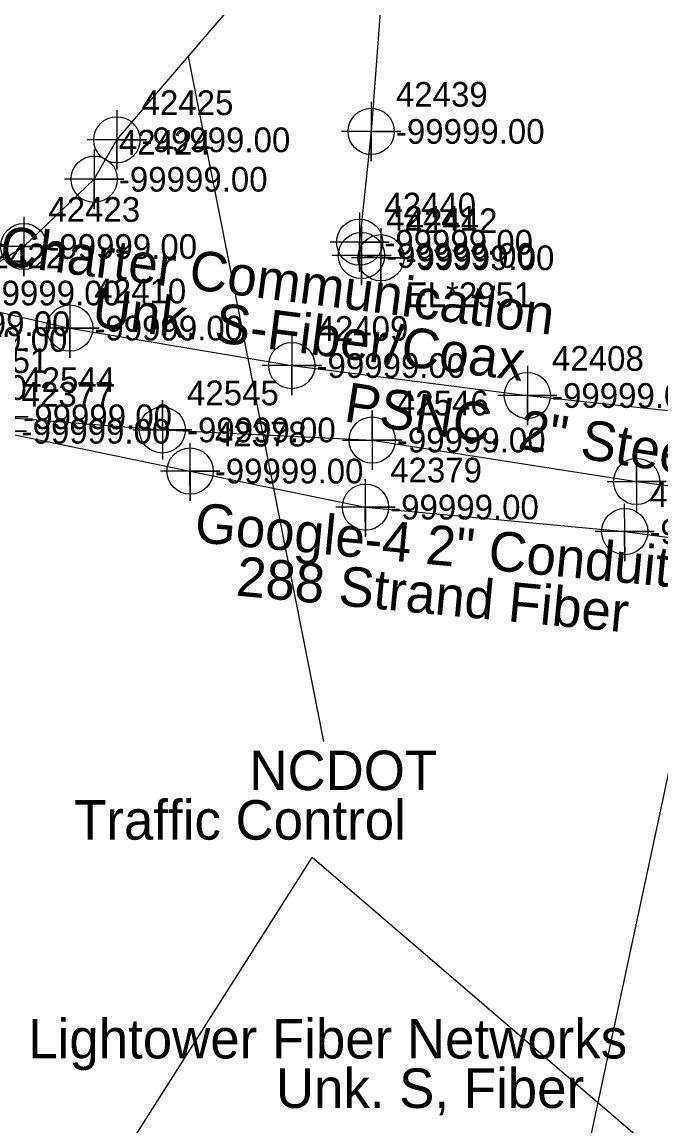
# Model space of a CAD drawing. Extents: x 2083698 to 2094313, y 743246 to 752873.
# Drawn here: x 2093709.1 to 2093773.8, y 746626.1 to 746737.9 of the extents above; entities that cross this region are included whole.
import ezdxf

# ---------------------------------------------------------------- set-up
doc = ezdxf.new("R2010")
doc.units = 0
for name, color, linetype in [('COGO Default Chain', 7, 'Continuous'), ('COGO Default Curve', 7, 'Continuous'), ('Default Symbol CELL', 7, 'Continuous'), ('Default Symbol Cogo Number', 7, 'Continuous'), ('Exist Property Iron Pin Leader', 7, 'Continuous'), ('Exist Property Iron Pin Text', 7, 'Continuous'), ('Exist Property Line Leader', 7, 'Continuous'), ('Exist Property Monument Leader', 7, 'Continuous'), ('Exist Property Monument Text', 7, 'Continuous'), ('Exist Right of Way Line Leader', 7, 'Continuous'), ('Exist Right of Way Line Text', 7, 'Continuous'), ('Exist Utilities Gas UG Line SUE LOS B', 7, 'Continuous'), ('Exist Utilities Gas UG Line SUE LOS B Text', 7, 'Continuous'), ('Exist Utilities Power Joint Use Telephone Cogo Elevation', 7, 'Continuous'), ('Exist Utilities Power UG Cable SUE LOS B', 7, 'Continuous'), ('Exist Utilities Power UG Cable SUE LOS B Leader', 7, 'Continuous'), ('Exist Utilities Power UG Cable SUE LOS B Text', 7, 'Continuous'), ('Exist Utilities Telephone UG Conduit SUE LOS B', 7, 'Continuous'), ('Exist Utilities Telephone UG Conduit SUE LOS B Text', 7, 'Continuous'), ('Exist Utilities TV UG Cable SUE LOS B', 7, 'Continuous'), ('Exist Utilities TV UG Cable SUE LOS B Text', 7, 'Continuous'), ('Exist Utilities Water UG Line SUE LOS B', 7, 'Continuous'), ('Old_Level_20', 7, 'Continuous'), ('Scratch_Level_2', 7, 'Continuous')]:
    doc.layers.add(name, color=color, linetype=linetype)

msp = doc.modelspace()

# ---------------------------------------------------------------- linework, layer by layer
at = {"layer": 'COGO Default Curve'}
for points in [[(2093703.71, 746697.9), (2093709.71, 746697.9), (2093706.71, 746697.9), (2093706.71, 746700.9), (2093706.71, 746694.9)], [(2093720.29, 746696.57), (2093726.29, 746696.57), (2093723.29, 746696.57), (2093723.29, 746699.57), (2093723.29, 746693.57)], [(2093741.54, 746695.55), (2093747.54, 746695.55), (2093744.54, 746695.55), (2093744.54, 746698.55), (2093744.54, 746692.55)], [(2093768.32, 746691.36), (2093774.32, 746691.36), (2093771.32, 746691.36), (2093771.32, 746694.36), (2093771.32, 746688.36)]]:
    msp.add_lwpolyline(points, dxfattribs=at)
for centre in [(2093723.29, 746696.57), (2093744.54, 746695.55), (2093771.32, 746691.36)]:
    msp.add_circle(centre, 2.34, dxfattribs=at)
at = {"layer": 'Exist Property Iron Pin Text'}
for points in [[(2093718.69, 746728.94), (2093718.69, 746722.94), (2093718.69, 746725.94), (2093721.69, 746725.94), (2093715.69, 746725.94)], [(2093744.44, 746729.79), (2093744.44, 746723.79), (2093744.44, 746726.79), (2093747.44, 746726.79), (2093741.44, 746726.79)], [(2093716.39, 746724.95), (2093716.39, 746718.95), (2093716.39, 746721.95), (2093719.39, 746721.95), (2093713.39, 746721.95)], [(2093709.25, 746718.14), (2093709.25, 746712.14), (2093709.25, 746715.14), (2093712.25, 746715.14), (2093706.25, 746715.14)], [(2093743.27, 746718.58), (2093743.27, 746712.58), (2093743.27, 746715.58), (2093746.27, 746715.58), (2093740.27, 746715.58)], [(2093743.45, 746717.23), (2093743.45, 746711.23), (2093743.45, 746714.23), (2093746.45, 746714.23), (2093740.45, 746714.23)], [(2093745.43, 746717), (2093745.43, 746711), (2093745.43, 746714), (2093748.43, 746714), (2093742.43, 746714)]]:
    msp.add_lwpolyline(points, dxfattribs=at)
for centre in [(2093744.44, 746726.79), (2093718.69, 746725.94), (2093716.39, 746721.95), (2093743.27, 746715.58), (2093709.25, 746715.14), (2093743.45, 746714.23), (2093745.43, 746714)]:
    msp.add_circle(centre, 2.34, dxfattribs=at)
at = {"layer": 'Exist Property Line Leader'}
for points in [[(2093713.91, 746709.88), (2093713.91, 746703.88), (2093713.91, 746706.88), (2093716.91, 746706.88), (2093710.91, 746706.88)], [(2093736.4, 746706.09), (2093736.4, 746700.09), (2093736.4, 746703.09), (2093739.4, 746703.09), (2093733.4, 746703.09)], [(2093760.25, 746703.06), (2093760.25, 746697.06), (2093760.25, 746700.06), (2093763.25, 746700.06), (2093757.25, 746700.06)]]:
    msp.add_lwpolyline(points, dxfattribs=at)
for centre in [(2093713.91, 746706.88), (2093736.4, 746703.09), (2093760.25, 746700.06)]:
    msp.add_circle(centre, 2.34, dxfattribs=at)
at = {"layer": 'Exist Right of Way Line Text'}
for points in [[(2093706.51, 746699.25), (2093706.54, 746693.44), (2093706.52, 746696.44), (2093709.54, 746696.44), (2093703.54, 746696.44)], [(2093726.07, 746695.23), (2093726.1, 746689.41), (2093726.09, 746692.41), (2093729.1, 746692.41), (2093723.1, 746692.41)], [(2093743.83, 746691.58), (2093743.86, 746685.76), (2093743.84, 746688.76), (2093746.86, 746688.76), (2093740.86, 746688.76)], [(2093770.07, 746689.09), (2093770.11, 746683.28), (2093770.09, 746686.28), (2093773.11, 746686.28), (2093767.11, 746686.28)]]:
    msp.add_lwpolyline(points, dxfattribs=at)
for centre in [(2093726.1, 746692.41), (2093743.86, 746688.76), (2093770.11, 746686.28)]:
    msp.add_circle(centre, 2.34, dxfattribs=at)
at = {"layer": 'Exist Utilities Gas UG Line SUE LOS B'}
msp.add_lwpolyline([(2093505.93, 746723.61), (2093532.22, 746720.11), (2093552.79, 746715.66), (2093607.51, 746708.06), (2093632.22, 746704.2), (2093661.04, 746701.95), (2093669.46, 746700.88), (2093683.89, 746699.44), (2093691.32, 746698.74), (2093706.71, 746697.9), (2093723.29, 746696.57), (2093744.54, 746695.55), (2093771.32, 746691.36), (2093802.14, 746687.34), (2093813.25, 746684.15), (2093821.63, 746681.65), (2093825.52, 746680.89), (2093827.42, 746680.73), (2093835.41, 746678.72), (2093847.6, 746678.13), (2093853.94, 746677.82), (2093882.08, 746674.68)], dxfattribs=at)
at = {"layer": 'Exist Utilities Power UG Cable SUE LOS B'}
for points in [[(2093696.42, 746707.33), (2093701.54, 746710.43), (2093709.25, 746715.14), (2093716.39, 746721.95), (2093718.69, 746725.94), (2093733.11, 746742.78), (2093736.3, 746751.06), (2093738.32, 746758.89), (2093740.41, 746760.24), (2093743.31, 746760.42)], [(2093744.43, 746760.29), (2093746.4, 746759.74), (2093745.51, 746741.12), (2093744.44, 746726.79), (2093743.27, 746715.58), (2093743.45, 746714.23), (2093745.43, 746714)]]:
    msp.add_lwpolyline(points, dxfattribs=at)
at = {"layer": 'Exist Utilities Power UG Cable SUE LOS B Leader'}
for p, q in [((2093725.9, 746734.36), (2093739.61, 746665.02)), ((2093697.6, 746589.02), (2093738.46, 746653.28)), ((2093791.38, 746607.89), (2093738.46, 746653.28))]:
    msp.add_line(p, q, dxfattribs=at)
at = {"layer": 'Exist Utilities Telephone UG Conduit SUE LOS B'}
msp.add_lwpolyline([(2093676.49, 746707.69), (2093692.01, 746700.86), (2093706.54, 746696.44), (2093726.1, 746692.41), (2093743.86, 746688.76), (2093770.11, 746686.28), (2093799.69, 746682.35), (2093807.44, 746680.69), (2093818.46, 746679.05), (2093846.17, 746679.15), (2093872.81, 746681.41), (2093899.4, 746682.12), (2093928.99, 746681.5), (2093976.67, 746681.24)], dxfattribs=at)
at = {"layer": 'Exist Utilities TV UG Cable SUE LOS B'}
msp.add_lwpolyline([(2093535.27, 746737.14), (2093544.69, 746734.46), (2093562.69, 746731.25), (2093584.23, 746728), (2093610.85, 746724.82), (2093638.4, 746722.42), (2093661.77, 746718.13), (2093688.25, 746712.71), (2093713.91, 746706.88), (2093736.4, 746703.09), (2093760.25, 746700.06), (2093787.85, 746697.12), (2093812.29, 746694.12), (2093831.84, 746693.64), (2093858.97, 746688.9), (2093882.24, 746685.84), (2093908.78, 746680.63), (2093912.93, 746679.95), (2093915.37, 746679.06)], dxfattribs=at)
at = {"layer": 'Exist Utilities Water UG Line SUE LOS B'}
msp.add_lwpolyline([(2093745.76, 746884.16), (2093757.71, 746850.49), (2093756.9, 746826.48), (2093756.29, 746805.81), (2093756.2, 746786.15), (2093756.77, 746780.86), (2093765.96, 746769.47), (2093770.41, 746764.53), (2093776.93, 746757.38), (2093786.5, 746749.39), (2093792.01, 746743.23), (2093788.01, 746735.45), (2093788.08, 746724.64), (2093787.59, 746718.51), (2093784.53, 746706.72), (2093782.33, 746698.29), (2093762.03, 746603.44)], dxfattribs=at)

# ---------------------------------------------------------------- texts
at = {"layer": 'COGO Default Chain'}
for p in [(2093709.21, 746696.65), (2093725.79, 746695.32), (2093747.04, 746694.3)]:
    msp.add_text('-99999.00', height=2.5, dxfattribs=at).set_placement(p)
at = {"layer": 'Default Symbol CELL'}
for s, p in [('42410', (2093716.41, 746709.38)), ('42409', (2093738.9, 746705.59)), ('42408', (2093762.75, 746702.56))]:
    msp.add_text(s, height=2.5, dxfattribs=at).set_placement(p)
at = {"layer": 'Default Symbol Cogo Number'}
for p in [(2093716.41, 746705.63), (2093738.9, 746701.84), (2093762.75, 746698.81)]:
    msp.add_text('-99999.00', height=2.5, dxfattribs=at).set_placement(p)
at = {"layer": 'Exist Property Iron Pin Leader'}
for s, p in [('42439', (2093746.94, 746729.29)), ('42425', (2093721.19, 746728.44)), ('42424', (2093718.89, 746724.45)), ('42423', (2093711.75, 746717.64)), ('42440', (2093745.77, 746718.08)), ('42441', (2093745.95, 746716.73)), ('42442', (2093747.93, 746716.5)), ('42422', (2093704.04, 746712.93))]:
    msp.add_text(s, height=2.5, dxfattribs=at).set_placement(p)
at = {"layer": 'Exist Property Monument Leader'}
for s, p in [('EL*2951', (2093747.93, 746709)), ('BL*2951', (2093698.92, 746702.33))]:
    msp.add_text(s, height=2.5, dxfattribs=at).set_placement(p)
at = {"layer": 'Exist Property Monument Text'}
for p in [(2093746.94, 746725.54), (2093721.19, 746724.69), (2093718.89, 746720.7), (2093745.77, 746714.33), (2093711.75, 746713.89), (2093745.95, 746712.98), (2093747.93, 746712.75), (2093704.04, 746709.18), (2093698.92, 746706.08)]:
    msp.add_text('-99999.00', height=2.5, dxfattribs=at).set_placement(p)
at = {"layer": 'Exist Right of Way Line Leader'}
for s, p in [('42377', (2093709.04, 746698.94)), ('42378', (2093728.6, 746694.91)), ('42379', (2093746.36, 746691.26)), ('42380', (2093772.61, 746688.78))]:
    msp.add_text(s, height=2.5, dxfattribs=at).set_placement(p)
at = {"layer": 'Exist Utilities Gas UG Line SUE LOS B Text'}
msp.add_text('PSNC, 2" Steel', height=4, rotation=351.1242, dxfattribs=at).set_placement((2093741.57, 746697.46))
at = {"layer": 'Exist Utilities Power Joint Use Telephone Cogo Elevation'}
msp.add_text('-99999.00', height=2.5, dxfattribs=at).set_placement((2093698.62, 746704.48))
at = {"layer": 'Exist Utilities Power UG Cable SUE LOS B Text'}
for s, p in [('NCDOT ', (2093732.1, 746660.11)), ('Traffic Control', (2093714.36, 746655.1))]:
    msp.add_text(s, height=4, dxfattribs=at).set_placement(p)
at = {"layer": 'Exist Utilities Telephone UG Conduit SUE LOS B Text'}
for s, p in [('Google-4 2" Conduits', (2093726.46, 746685.24)), ('288 Strand Fiber', (2093730.65, 746679.82))]:
    msp.add_text(s, height=4, rotation=354.5931, dxfattribs=at).set_placement(p)
for s, p in [('Lightower Fiber Networks', (2093709.71, 746632.95)), ('Unk. S, Fiber', (2093734.79, 746627.94))]:
    msp.add_text(s, height=4, dxfattribs=at).set_placement(p)
at = {"layer": 'Exist Utilities TV UG Cable SUE LOS B Text'}
for s, p in [('Charter Communication', (2093706.69, 746713.3)), ('Unk. S-Fiber/Coax', (2093716.06, 746707.06))]:
    msp.add_text(s, height=4, rotation=352.7662, dxfattribs=at).set_placement(p)
at = {"layer": 'Old_Level_20'}
for s, p in [('42544', (2093709.21, 746700.4)), ('42545', (2093725.79, 746699.07)), ('42546', (2093747.04, 746698.05))]:
    msp.add_text(s, height=2.5, dxfattribs=at).set_placement(p)
at = {"layer": 'Scratch_Level_2'}
for p in [(2093694.51, 746699.61), (2093709.04, 746695.19), (2093728.6, 746691.16), (2093746.36, 746687.51), (2093772.61, 746685.03)]:
    msp.add_text('-99999.00', height=2.5, dxfattribs=at).set_placement(p)

doc.saveas('drawing.dxf')
